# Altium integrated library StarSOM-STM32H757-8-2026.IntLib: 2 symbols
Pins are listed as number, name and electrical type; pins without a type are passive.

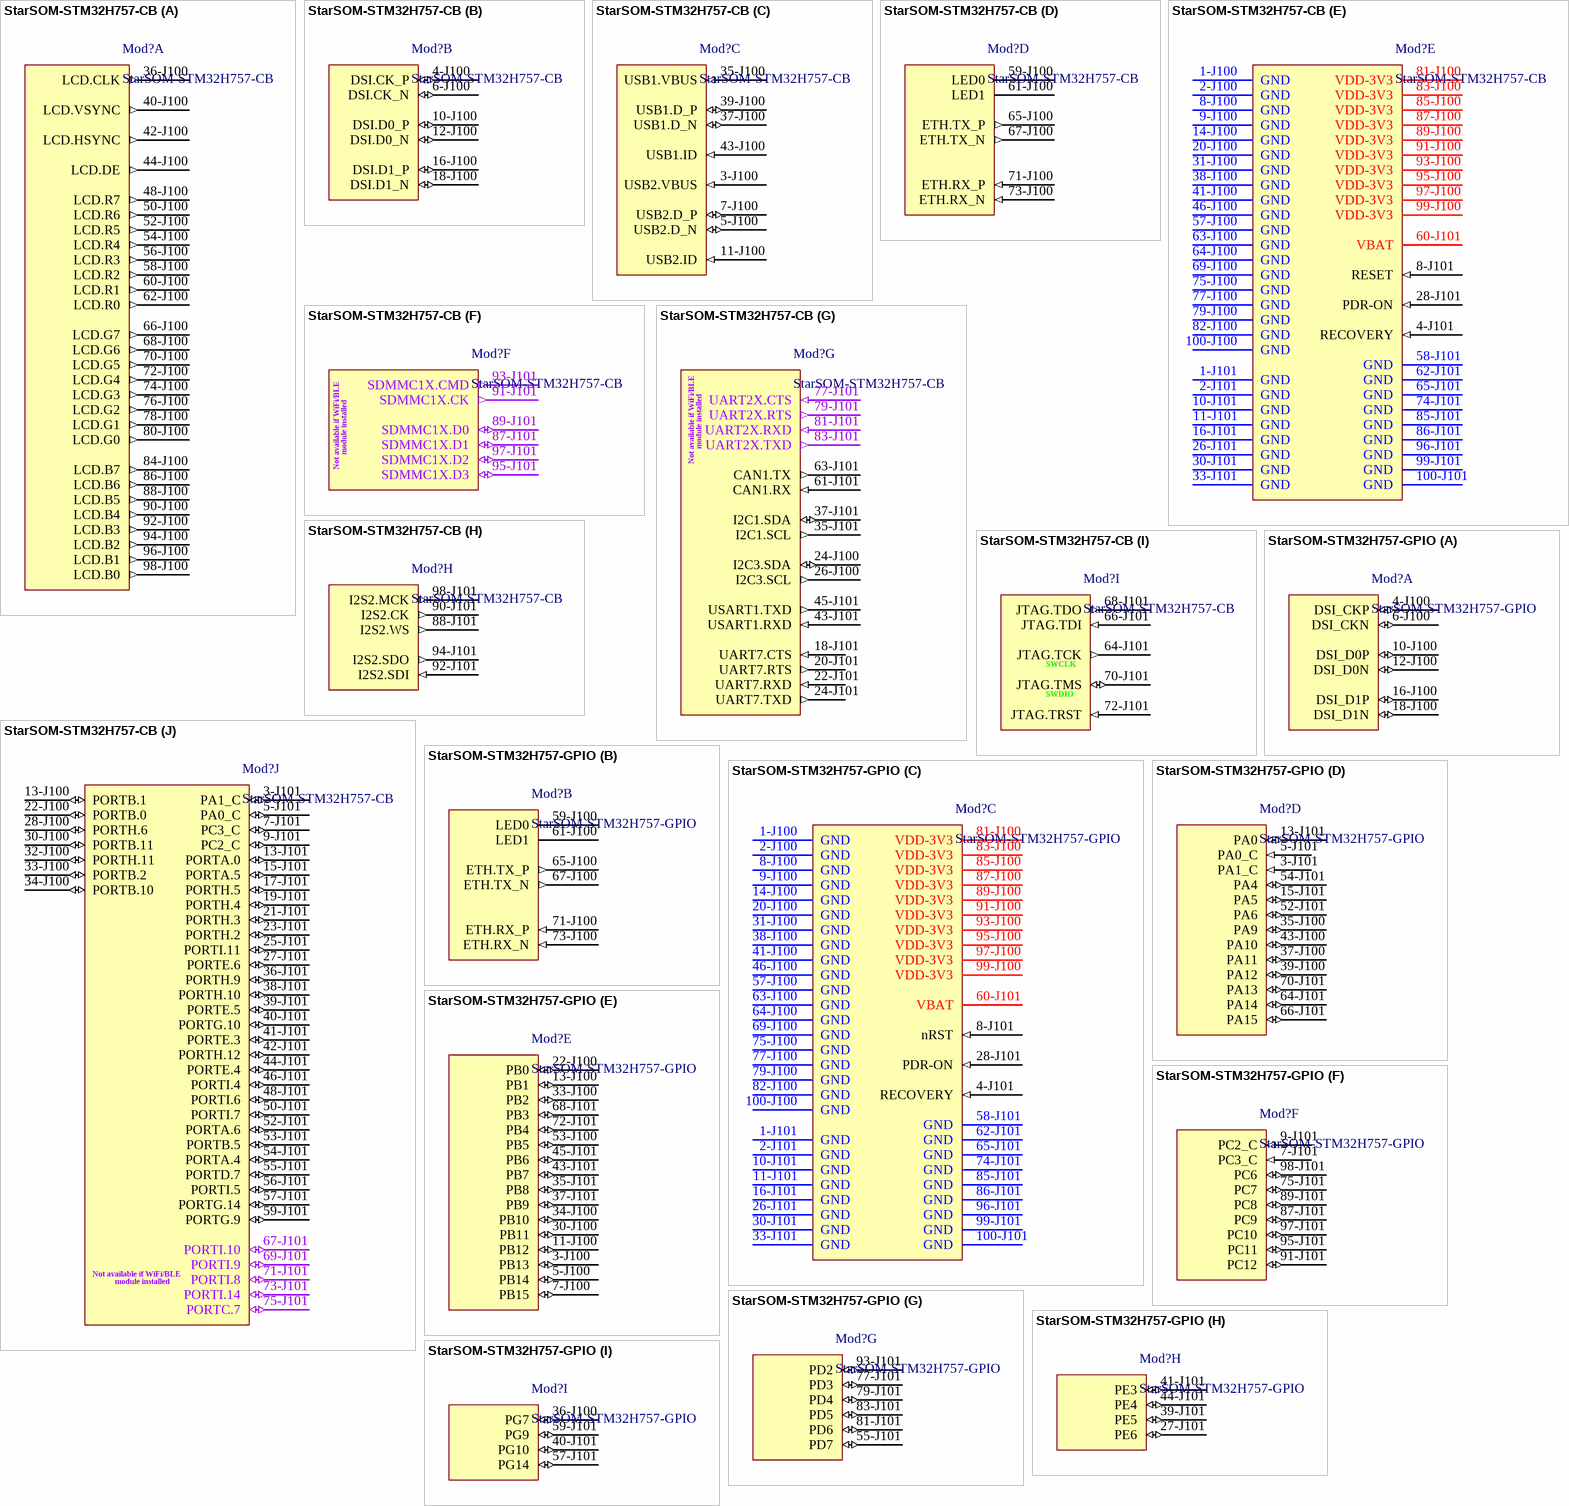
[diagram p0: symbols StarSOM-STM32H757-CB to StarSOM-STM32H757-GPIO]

## StarSOM-STM32H757-CB
designator Mod?
StarSOM-STM32H757 schematic model with pins view in functional assignments for peripherals of StarCB-STM32H757-STD
footprint StarSOM-STM32H757 (Footprint of StarSOM-STM32H757. / B2B connectors are Hirose DF40C-100DP-0.4V(51) (2 pcs))
part A pins: 36-J100 LCD.CLK (out), 40-J100 LCD.VSYNC (out), 42-J100 LCD.HSYNC (out), 44-J100 LCD.DE (out), 48-J100 LCD.R7 (out), 50-J100 LCD.R6 (out), 52-J100 LCD.R5 (out), 54-J100 LCD.R4 (out), 56-J100 LCD.R3 (out), 58-J100 LCD.R2 (out), 60-J100 LCD.R1 (out), 62-J100 LCD.R0 (out), 66-J100 LCD.G7 (out), 68-J100 LCD.G6 (out), 70-J100 LCD.G5 (out), 72-J100 LCD.G4 (out), 74-J100 LCD.G3 (out), 76-J100 LCD.G2 (out), 78-J100 LCD.G1 (out), 80-J100 LCD.G0 (out), 84-J100 LCD.B7 (out), 86-J100 LCD.B6 (out), 88-J100 LCD.B5 (out), 90-J100 LCD.B4 (out), 92-J100 LCD.B3 (out), 94-J100 LCD.B2 (out), 96-J100 LCD.B1 (out), 98-J100 LCD.B0 (out)
part B pins: 4-J100 DSI.CK_P (io), 6-J100 DSI.CK_N (io), 10-J100 DSI.D0_P (io), 12-J100 DSI.D0_N (io), 16-J100 DSI.D1_P (io), 18-J100 DSI.D1_N (io)
part C pins: 3-J100 USB2.VBUS (in), 5-J100 USB2.D_N (io), 7-J100 USB2.D_P (io), 11-J100 USB2.ID (in), 35-J100 USB1.VBUS (in), 37-J100 USB1.D_N (io), 39-J100 USB1.D_P (io), 43-J100 USB1.ID (in)
part D pins: 59-J100 LED0 (oc), 61-J100 LED1 (oc), 65-J100 ETH.TX_P (out), 67-J100 ETH.TX_N (out), 71-J100 ETH.RX_P (in), 73-J100 ETH.RX_N (in)
part E pins: 1-J100 GND (power), 1-J101 GND (power), 2-J100 GND (power), 2-J101 GND (power), 4-J101 RECOVERY (in), 8-J100 GND (power), 8-J101 RESET (in), 9-J100 GND (power), 10-J101 GND (power), 11-J101 GND (power), 14-J100 GND (power), 16-J101 GND (power), 20-J100 GND (power), 26-J101 GND (power), 28-J101 PDR-ON (in), 30-J101 GND (power), 31-J100 GND (power), 33-J101 GND (power), 38-J100 GND (power), 41-J100 GND (power), 46-J100 GND (power), 57-J100 GND (power), 58-J101 GND (power), 60-J101 VBAT (power), 62-J101 GND (power), 63-J100 GND (power), 64-J100 GND (power), 65-J101 GND (power), 69-J100 GND (power), 74-J101 GND (power), 75-J100 GND (power), 77-J100 GND (power), 79-J100 GND (power), 81-J100 VDD-3V3 (power), 82-J100 GND (power), 83-J100 VDD-3V3 (power), 85-J100 VDD-3V3 (power), 85-J101 GND (power), 86-J101 GND (power), 87-J100 VDD-3V3 (power), 89-J100 VDD-3V3 (power), 91-J100 VDD-3V3 (power), 93-J100 VDD-3V3 (power), 95-J100 VDD-3V3 (power), 96-J101 GND (power), 97-J100 VDD-3V3 (power), 99-J100 VDD-3V3 (power), 99-J101 GND (power), 100-J100 GND (power), 100-J101 GND (power)
part F pins: 87-J101 SDMMC1X.D1 (io), 89-J101 SDMMC1X.D0 (io), 91-J101 SDMMC1X.CK (out), 93-J101 SDMMC1X.CMD (out), 95-J101 SDMMC1X.D3 (io), 97-J101 SDMMC1X.D2 (io)
part G pins: 18-J101 UART7.CTS (in), 20-J101 UART7.RTS (out), 22-J101 UART7.RXD (in), 24-J100 I2C3.SDA (io), 24-J101 UART7.TXD (out), 26-J100 I2C3.SCL (out), 35-J101 I2C1.SCL (out), 37-J101 I2C1.SDA (io), 43-J101 USART1.RXD (in), 45-J101 USART1.TXD (out), 61-J101 CAN1.RX (in), 63-J101 CAN1.TX (out), 77-J101 UART2X.CTS (in), 79-J101 UART2X.RTS (out), 81-J101 UART2X.RXD (in), 83-J101 UART2X.TXD (out)
part H pins: 88-J101 I2S2.WS (out), 90-J101 I2S2.CK (out), 92-J101 I2S2.SDI (in), 94-J101 I2S2.SDO (out), 98-J101 I2S2.MCK (out)
part I pins: 64-J101 JTAG.TCK (out), 66-J101 JTAG.TDI (in), 68-J101 JTAG.TDO (out), 70-J101 JTAG.TMS (io), 72-J101 JTAG.TRST (in)
part J pins: 3-J101 PA1_C (io), 5-J101 PA0_C (io), 7-J101 PC3_C (io), 9-J101 PC2_C (io), 13-J100 PORTB.1 (io), 13-J101 PORTA.0 (io), 15-J101 PORTA.5 (io), 17-J101 PORTH.5 (io), 19-J101 PORTH.4 (io), 21-J101 PORTH.3 (io), 22-J100 PORTB.0 (io), 23-J101 PORTH.2 (io), 25-J101 PORTI.11 (io), 27-J101 PORTE.6 (io), 28-J100 PORTH.6 (io), 30-J100 PORTB.11 (io), 32-J100 PORTH.11 (io), 33-J100 PORTB.2 (io), 34-J100 PORTB.10 (io), 36-J101 PORTH.9 (io), 38-J101 PORTH.10 (io), 39-J101 PORTE.5 (io), 40-J101 PORTG.10 (io), 41-J101 PORTE.3 (io), 42-J101 PORTH.12 (io), 44-J101 PORTE.4 (io), 46-J101 PORTI.4 (io), 48-J101 PORTI.6 (io), 50-J101 PORTI.7 (io), 52-J101 PORTA.6 (io), 53-J101 PORTB.5 (io), 54-J101 PORTA.4 (io), 55-J101 PORTD.7 (io), 56-J101 PORTI.5 (io), 57-J101 PORTG.14 (io), 59-J101 PORTG.9 (io), 67-J101 PORTI.10 (io), 69-J101 PORTI.9 (io), 71-J101 PORTI.8 (io), 73-J101 PORTI.14 (io), 75-J101 PORTC.7 (io)

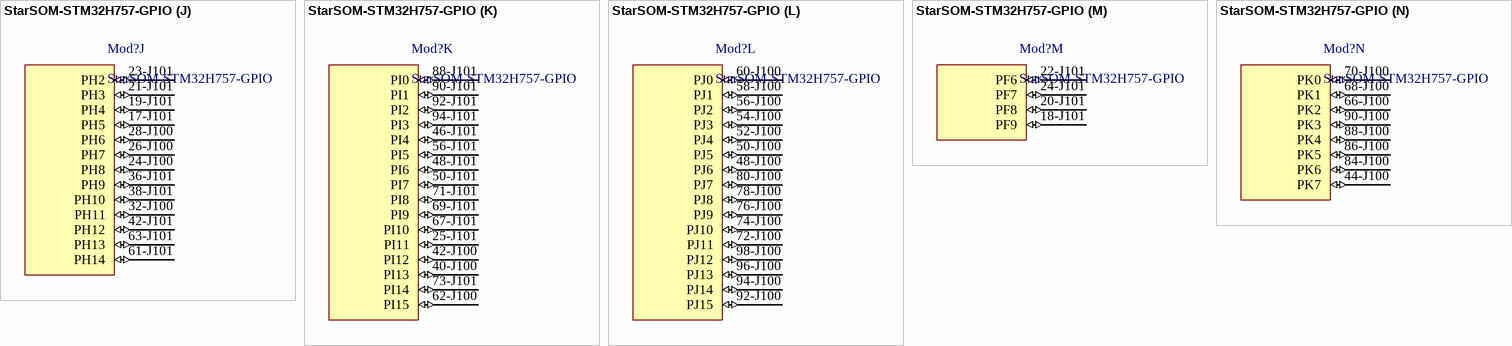
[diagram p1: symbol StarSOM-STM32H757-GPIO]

## StarSOM-STM32H757-GPIO
designator Mod?
StarSOM-STM32H757 schematic model with pins view in GPIO mode
footprint STARSOM-STM32H757 (Footprint of StarSOM-STM32H757. / B2B connectors are Hirose DF40C-100DP-0.4V(51) (2 pcs))
part A pins: 4-J100 DSI_CKP (io), 6-J100 DSI_CKN (io), 10-J100 DSI_D0P (io), 12-J100 DSI_D0N (io), 16-J100 DSI_D1P (io), 18-J100 DSI_D1N (io)
part B pins: 59-J100 LED0 (oc), 61-J100 LED1 (oc), 65-J100 ETH.TX_P (out), 67-J100 ETH.TX_N (out), 71-J100 ETH.RX_P (in), 73-J100 ETH.RX_N (in)
part C pins: 1-J100 GND (power), 1-J101 GND (power), 2-J100 GND (power), 2-J101 GND (power), 4-J101 RECOVERY (in), 8-J100 GND (power), 8-J101 nRST (in), 9-J100 GND (power), 10-J101 GND (power), 11-J101 GND (power), 14-J100 GND (power), 16-J101 GND (power), 20-J100 GND (power), 26-J101 GND (power), 28-J101 PDR-ON (in), 30-J101 GND (power), 31-J100 GND (power), 33-J101 GND (power), 38-J100 GND (power), 41-J100 GND (power), 46-J100 GND (power), 57-J100 GND (power), 58-J101 GND (power), 60-J101 VBAT (power), 62-J101 GND (power), 63-J100 GND (power), 64-J100 GND (power), 65-J101 GND (power), 69-J100 GND (power), 74-J101 GND (power), 75-J100 GND (power), 77-J100 GND (power), 79-J100 GND (power), 81-J100 VDD-3V3 (power), 82-J100 GND (power), 83-J100 VDD-3V3 (power), 85-J100 VDD-3V3 (power), 85-J101 GND (power), 86-J101 GND (power), 87-J100 VDD-3V3 (power), 89-J100 VDD-3V3 (power), 91-J100 VDD-3V3 (power), 93-J100 VDD-3V3 (power), 95-J100 VDD-3V3 (power), 96-J101 GND (power), 97-J100 VDD-3V3 (power), 99-J100 VDD-3V3 (power), 99-J101 GND (power), 100-J100 GND (power), 100-J101 GND (power)
part D pins: 3-J101 PA1_C (in), 5-J101 PA0_C (in), 13-J101 PA0 (io), 15-J101 PA5 (io), 35-J100 PA9 (io), 37-J100 PA11 (io), 39-J100 PA12 (io), 43-J100 PA10 (io), 52-J101 PA6 (io), 54-J101 PA4 (io), 64-J101 PA14 (io), 66-J101 PA15 (io), 70-J101 PA13 (io)
part E pins: 3-J100 PB13 (io), 5-J100 PB14 (io), 7-J100 PB15 (io), 11-J100 PB12 (io), 13-J100 PB1 (io), 22-J100 PB0 (io), 30-J100 PB11 (io), 33-J100 PB2 (io), 34-J100 PB10 (io), 35-J101 PB8 (io), 37-J101 PB9 (io), 43-J101 PB7 (io), 45-J101 PB6 (io), 53-J100 PB5 (io), 68-J101 PB3 (io), 72-J101 PB4 (io)
part F pins: 7-J101 PC3_C (in), 9-J101 PC2_C (in), 75-J101 PC7 (io), 87-J101 PC9 (io), 89-J101 PC8 (io), 91-J101 PC12 (io), 95-J101 PC11 (io), 97-J101 PC10 (io), 98-J101 PC6 (io)
part G pins: 55-J101 PD7 (io), 77-J101 PD3 (io), 79-J101 PD4 (io), 81-J101 PD6 (io), 83-J101 PD5 (io), 93-J101 PD2 (io)
part H pins: 27-J101 PE6 (io), 39-J101 PE5 (io), 41-J101 PE3 (io), 44-J101 PE4 (io)
part I pins: 36-J100 PG7 (io), 40-J101 PG10 (io), 57-J101 PG14 (io), 59-J101 PG9 (io)
part J pins: 17-J101 PH5 (io), 19-J101 PH4 (io), 21-J101 PH3 (io), 23-J101 PH2 (io), 24-J100 PH8 (io), 26-J100 PH7 (io), 28-J100 PH6 (io), 32-J100 PH11 (io), 36-J101 PH9 (io), 38-J101 PH10 (io), 42-J101 PH12 (io), 61-J101 PH14 (io), 63-J101 PH13 (io)
part K pins: 25-J101 PI11 (io), 40-J100 PI13 (io), 42-J100 PI12 (io), 46-J101 PI4 (io), 48-J101 PI6 (io), 50-J101 PI7 (io), 56-J101 PI5 (io), 62-J100 PI15 (io), 67-J101 PI10 (io), 69-J101 PI9 (io), 71-J101 PI8 (io), 73-J101 PI14 (io), 88-J101 PI0 (io), 90-J101 PI1 (io), 92-J101 PI2 (io), 94-J101 PI3 (io)
part L pins: 48-J100 PJ6 (io), 50-J100 PJ5 (io), 52-J100 PJ4 (io), 54-J100 PJ3 (io), 56-J100 PJ2 (io), 58-J100 PJ1 (io), 60-J100 PJ0 (io), 72-J100 PJ11 (io), 74-J100 PJ10 (io), 76-J100 PJ9 (io), 78-J100 PJ8 (io), 80-J100 PJ7 (io), 92-J100 PJ15 (io), 94-J100 PJ14 (io), 96-J100 PJ13 (io), 98-J100 PJ12 (io)
part M pins: 18-J101 PF9 (io), 20-J101 PF8 (io), 22-J101 PF6 (io), 24-J101 PF7 (io)
part N pins: 44-J100 PK7 (io), 66-J100 PK2 (io), 68-J100 PK1 (io), 70-J100 PK0 (io), 84-J100 PK6 (io), 86-J100 PK5 (io), 88-J100 PK4 (io), 90-J100 PK3 (io)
